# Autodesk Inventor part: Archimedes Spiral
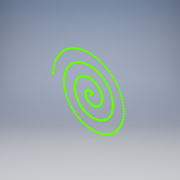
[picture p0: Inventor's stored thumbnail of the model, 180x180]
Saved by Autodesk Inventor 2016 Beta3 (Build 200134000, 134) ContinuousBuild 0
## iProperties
Created: 2008-02
Part Number: Archimedes Spiral
Document SubType Name: Modeling
Designer: Autodesk, Inc.
Density: 1 g/cm^3
Material: Generic
Appearance: Default
Author: Autodesk, Inc.
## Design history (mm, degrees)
sketch "Sketch1"
  geometry: 300 further points
  constraints: 300 other
